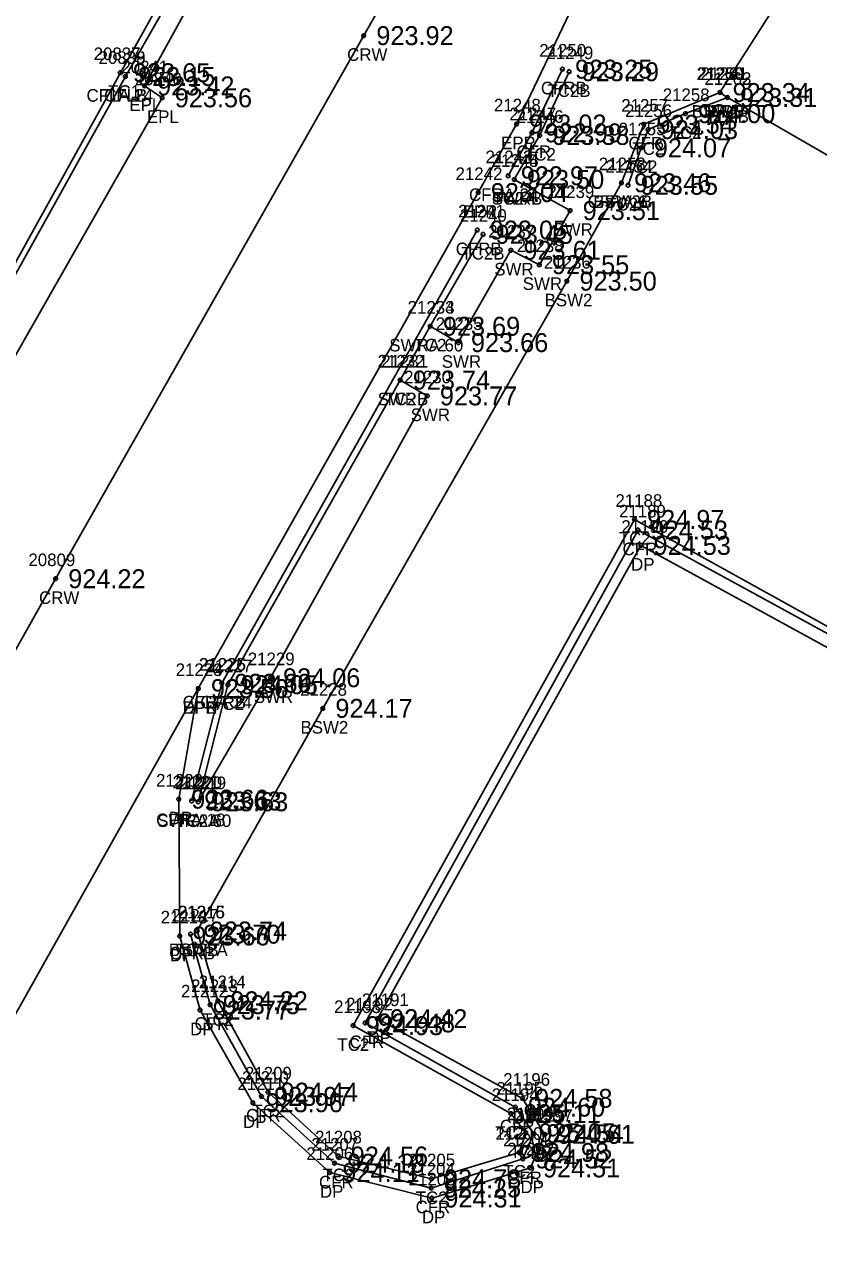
# Model space of a CAD drawing. Extents: x 1576181 to 1577685, y 1099396 to 1101490.
# Drawn here: x 1576844.5 to 1576907.5, y 1100279.9 to 1100377.3 of the extents above; entities that cross this region are included whole.
import ezdxf

# ---------------------------------------------------------------- set-up
doc = ezdxf.new("R2010")
doc.units = 0
for name, color, linetype in [('RD_DTM_BkLn1', 7, 'Continuous'), ('RD_DTM_BkLn2', 7, 'Continuous'), ('RD_EX_Conc', 7, 'Continuous'), ('RD_EX_Conc_txCode', 7, 'Continuous'), ('RD_EX_Driveway', 7, 'Continuous'), ('RD_EX_Driveway_txCode', 7, 'Continuous'), ('RD_EX_Road', 7, 'Continuous'), ('RD_EX_Road_txCode', 7, 'Continuous'), ('RD_EX_TX_Conc_ELEV', 7, 'Continuous'), ('RD_EX_TX_Driveway_ELEV', 7, 'Continuous'), ('RD_EX_TX_Road_ELEV', 7, 'Continuous'), ('RD_HC_Survey_ELEV', 7, 'Continuous'), ('RD_HC_Survey_txCode', 7, 'Continuous'), ('RD_SMD_Locator', 7, 'Continuous')]:
    doc.layers.add(name, color=color, linetype=linetype)

msp = doc.modelspace()

# ---------------------------------------------------------------- linework, layer by layer
at = {"layer": 'RD_DTM_BkLn1'}
msp.add_lwpolyline([(1576435.959, 1099635.472), (1576469.98, 1099685.91), (1576496.508, 1099728.461), (1576522.669, 1099770.846), (1576549.059, 1099813.404), (1576563.36, 1099837.201), (1576575.086, 1099855.947), (1576600.753, 1099898.956), (1576625.567, 1099942.138), (1576652.375, 1099988.914), (1576675.029, 1100029.122), (1576699.512, 1100072.437), (1576723.525, 1100115.704), (1576748.078, 1100158.53), (1576774.135, 1100203.854), (1576797.974, 1100246.518), (1576822.461, 1100289.822), (1576846.927, 1100333.353), (1576871.373, 1100376.464), (1576888.271, 1100406.22)], dxfattribs=at)
at = {"layer": 'RD_DTM_BkLn2'}
for points in [[(1576569.711, 1099889.13), (1576574.557, 1099891.336), (1576579.266, 1099894.472), (1576584.192, 1099899.549), (1576592.247, 1099913.589), (1576612.839, 1099949.867), (1576637.542, 1099993.053), (1576637.542, 1099993.053), (1576662.194, 1100036.338), (1576686.674, 1100079.686), (1576711.458, 1100123.123), (1576735.923, 1100166.594), (1576760.755, 1100210.189), (1576785.214, 1100253.551), (1576809.128, 1100296.431), (1576833.847, 1100340.609), (1576852.062, 1100373.523), (1576858.657, 1100385.374)], [(1576883.322, 1100365.048), (1576885.33, 1100368.539), (1576887.663, 1100373.598)], [(1576892.348, 1100364.583), (1576893.39, 1100367.555), (1576893.933, 1100369.003), (1576896.892, 1100370.27), (1576900.229, 1100371.557)], [(1576858.248, 1100315.646), (1576860.602, 1100324.935), (1576874.266, 1100349.12), (1576876.652, 1100353.396), (1576880.838, 1100360.691)], [(1576981.641, 1100308.772), (1576944.221, 1100331.974), (1576924.823, 1100343.94), (1576916.376, 1100330.898), (1576913.272, 1100328.019), (1576909.644, 1100328.751), (1576892.858, 1100338.06), (1576870.533, 1100297.878), (1576883.045, 1100290.892), (1576884.239, 1100289.373), (1576883.702, 1100287.814), (1576876.741, 1100285.714), (1576869.346, 1100287.53), (1576863.783, 1100292.601), (1576859.799, 1100299.85), (1576858.159, 1100305.393)]]:
    msp.add_lwpolyline(points, dxfattribs=at)
at = {"layer": 'RD_EX_Conc'}
for points in [[(1576569.868, 1099888.686), (1576574.844, 1099890.862), (1576574.844, 1099890.862), (1576579.65, 1099894.152), (1576584.72, 1099899.292), (1576592.679, 1099913.301), (1576613.452, 1099949.723), (1576638.024, 1099992.781), (1576638.024, 1099992.781), (1576662.599, 1100036.053), (1576687.141, 1100079.444), (1576711.907, 1100122.93), (1576736.416, 1100166.347), (1576761.24, 1100209.96), (1576785.667, 1100253.173), (1576809.571, 1100296.248), (1576834.314, 1100340.558), (1576852.459, 1100373.219), (1576852.459, 1100373.219), (1576859.244, 1100385.101)], [(1576899.64, 1100371.947), (1576906.579, 1100382.841), (1576904.274, 1100384.162), (1576904.199, 1100384.423)], [(1576882.832, 1100365.339), (1576884.725, 1100368.746), (1576887.135, 1100373.802)], [(1576891.82, 1100364.783), (1576893.604, 1100369.429), (1576899.64, 1100371.947)], [(1576876.652, 1100353.396), (1576878.88, 1100352.096), (1576883.047, 1100359.426), (1576885.307, 1100358.28), (1576887.745, 1100362.574), (1576883.322, 1100365.048)], [(1576858.159, 1100305.393), (1576868.123, 1100323.063), (1576887.49, 1100356.975), (1576891.82, 1100364.783)], [(1576857.719, 1100315.713), (1576860.106, 1100325.056), (1576860.106, 1100325.056), (1576880.379, 1100361.032)], [(1576858.248, 1100315.646), (1576863.967, 1100325.491), (1576876.416, 1100347.866), (1576874.266, 1100349.12)], [(1576981.4, 1100308.175), (1576943.854, 1100331.434), (1576924.982, 1100343.186), (1576916.835, 1100330.69), (1576913.186, 1100327.347), (1576909.365, 1100328.339), (1576893.139, 1100337.219), (1576871.484, 1100298.091), (1576883.401, 1100291.404), (1576884.862, 1100289.303), (1576883.985, 1100287.299), (1576876.72, 1100284.984), (1576869.052, 1100286.957), (1576863.263, 1100292.262), (1576859.183, 1100299.543), (1576857.641, 1100305.136)]]:
    msp.add_lwpolyline(points, dxfattribs=at)
at = {"layer": 'RD_EX_Driveway'}
for points in [[(1576899.64, 1100371.947), (1576900.229, 1100371.557), (1576947.086, 1100344.489), (1576990.818, 1100317.698)], [(1576980.993, 1100307.534), (1576943.247, 1100330.682), (1576925.325, 1100342), (1576917.589, 1100330.217), (1576913.446, 1100326.455), (1576909.081, 1100327.403), (1576893.369, 1100335.997), (1576872.46, 1100298.43), (1576883.975, 1100292.106), (1576885.751, 1100289.247), (1576884.594, 1100286.58), (1576876.771, 1100284.193), (1576868.68, 1100286.222), (1576862.578, 1100291.757), (1576858.385, 1100299.115), (1576856.774, 1100304.988), (1576856.691, 1100315.855), (1576858.248, 1100324.631)]]:
    msp.add_lwpolyline(points, dxfattribs=at)
at = {"layer": 'RD_EX_Road'}
for points in [[(1576574.844, 1099890.862), (1576581.171, 1099887.16), (1576595.394, 1099911.974), (1576615.874, 1099948.174), (1576640.557, 1099991.404), (1576640.557, 1099991.404), (1576664.878, 1100034.189), (1576689.843, 1100078.058), (1576714.218, 1100121.186), (1576739.079, 1100164.658), (1576764.147, 1100209.109), (1576788.309, 1100251.8), (1576812.145, 1100294.456), (1576837.057, 1100339.374), (1576855.378, 1100371.527), (1576853.98, 1100372.475), (1576862.984, 1100388.862), (1576865.16, 1100391.948), (1576873.145, 1100402.798), (1576877.449, 1100410.316)], [(1576663.307, 1099979.534), (1576687.432, 1100021.526), (1576712.032, 1100065.104), (1576738.416, 1100112.144), (1576760.611, 1100151.412), (1576785.777, 1100195.961), (1576800.589, 1100221.872), (1576817.543, 1100252.084), (1576858.248, 1100324.631), (1576880.454, 1100364.005), (1576883.5, 1100369.448), (1576896.98, 1100397.709)]]:
    msp.add_lwpolyline(points, dxfattribs=at)
at = {"layer": 'RD_SMD_Locator'}
for centre in [(1576871.373, 1100376.464), (1576887.135, 1100373.802), (1576887.663, 1100373.598), (1576852.062, 1100373.523), (1576852.459, 1100373.219), (1576852.459, 1100373.219), (1576853.98, 1100372.475), (1576899.64, 1100371.947), (1576899.64, 1100371.947), (1576899.64, 1100371.947), (1576855.378, 1100371.527), (1576900.229, 1100371.557), (1576900.229, 1100371.557), (1576896.892, 1100370.27), (1576883.5, 1100369.448), (1576884.725, 1100368.746), (1576893.604, 1100369.429), (1576893.933, 1100369.003), (1576885.33, 1100368.539), (1576893.39, 1100367.555), (1576882.832, 1100365.339), (1576883.322, 1100365.048), (1576883.322, 1100365.048), (1576891.82, 1100364.783), (1576891.82, 1100364.783), (1576880.454, 1100364.005), (1576892.348, 1100364.583), (1576887.745, 1100362.574), (1576880.379, 1100361.032), (1576880.838, 1100360.691), (1576883.047, 1100359.426), (1576885.307, 1100358.28), (1576887.49, 1100356.975), (1576876.652, 1100353.396), (1576876.652, 1100353.396), (1576878.88, 1100352.096), (1576874.266, 1100349.12), (1576874.266, 1100349.12), (1576876.416, 1100347.866), (1576892.858, 1100338.06), (1576893.139, 1100337.219), (1576893.369, 1100335.997), (1576846.927, 1100333.353), (1576860.106, 1100325.056), (1576860.106, 1100325.056), (1576860.602, 1100324.935), (1576863.967, 1100325.491), (1576858.248, 1100324.631), (1576858.248, 1100324.631), (1576868.123, 1100323.063), (1576856.691, 1100315.855), (1576857.719, 1100315.713), (1576858.248, 1100315.646), (1576858.248, 1100315.646), (1576858.159, 1100305.393), (1576858.159, 1100305.393), (1576856.774, 1100304.988), (1576857.641, 1100305.136), (1576859.183, 1100299.543), (1576859.799, 1100299.85), (1576858.385, 1100299.115), (1576870.533, 1100297.878), (1576871.484, 1100298.091), (1576872.46, 1100298.43), (1576862.578, 1100291.757), (1576863.263, 1100292.262), (1576863.783, 1100292.601), (1576883.975, 1100292.106), (1576883.045, 1100290.892), (1576883.401, 1100291.404), (1576884.239, 1100289.373), (1576884.862, 1100289.303), (1576885.751, 1100289.247), (1576883.702, 1100287.814), (1576869.052, 1100286.957), (1576869.346, 1100287.53), (1576883.985, 1100287.299), (1576868.68, 1100286.222), (1576884.594, 1100286.58), (1576876.72, 1100284.984), (1576876.741, 1100285.714), (1576876.771, 1100284.193)]:
    msp.add_circle(centre, 0.15, dxfattribs=at)

# ---------------------------------------------------------------- texts
at = {"layer": 'RD_EX_Conc_txCode'}
for s, p in [('21250', (1576885.301, 1100374.802)), ('20837', (1576849.944, 1100374.523)), ('20838', (1576850.34, 1100374.219)), ('20839', (1576850.34, 1100374.219)), ('21249', (1576885.868, 1100374.598)), ('21260', (1576897.781, 1100372.947)), ('21259', (1576897.844, 1100372.947)), ('CFRB', (1576885.434, 1100371.802)), ('21263', (1576898.411, 1100372.557)), ('CFLA 24', (1576849.38, 1100371.219)), ('CFLB', (1576850.781, 1100371.219)), ('TC1', (1576851.101, 1100371.523)), ('TC2B', (1576885.947, 1100371.598)), ('21258', (1576895.097, 1100371.27)), ('21257', (1576891.809, 1100370.429)), ('21256', (1576892.115, 1100370.003)), ('BSW2A', (1576897.388, 1100369.947)), ('CFRB', (1576897.939, 1100369.947)), ('21247', (1576882.93, 1100369.746)), ('21246', (1576883.511, 1100369.539)), ('TC2B', (1576898.513, 1100369.557)), ('21255', (1576891.595, 1100368.555)), ('TC2', (1576895.648, 1100368.27)), ('CFR', (1576892.375, 1100367.429)), ('TC2', (1576892.689, 1100367.003)), ('21243', (1576881.036, 1100366.339)), ('21244', (1576881.526, 1100366.048)), ('21245', (1576881.526, 1100366.048)), ('CFR', (1576883.497, 1100366.746)), ('TC2', (1576884.086, 1100366.539)), ('21252', (1576890.024, 1100365.783)), ('21253', (1576890.024, 1100365.783)), ('21254', (1576890.553, 1100365.583)), ('TC2', (1576892.146, 1100365.555)), ('CFRA 24', (1576879.729, 1100363.339)), ('SWRB', (1576881.534, 1100363.048)), ('TC2A', (1576881.589, 1100363.048)), ('21239', (1576885.95, 1100363.574)), ('21241', (1576878.867, 1100362.032)), ('CFRA 6', (1576889.143, 1100362.783)), ('BSW2B', (1576889.583, 1100362.783)), ('TC2A', (1576890.616, 1100362.583)), ('21240', (1576879.004, 1100361.691)), ('21237', (1576881.252, 1100360.426)), ('SWR', (1576886.43, 1100360.574)), ('21238', (1576883.512, 1100359.28)), ('CFRB', (1576878.678, 1100359.032)), ('TC2B', (1576879.122, 1100358.691)), ('SWR', (1576881.732, 1100357.426)), ('21236', (1576885.671, 1100357.975)), ('SWR', (1576883.992, 1100356.28)), ('21233', (1576874.857, 1100354.396)), ('21234', (1576874.857, 1100354.396)), ('BSW2', (1576885.726, 1100354.975)), ('21235', (1576877.085, 1100353.096)), ('SWRA 60', (1576873.4, 1100351.396)), ('TC2', (1576875.408, 1100351.396)), ('21232', (1576872.471, 1100350.12)), ('21231', (1576872.754, 1100350.12)), ('SWR', (1576877.565, 1100350.096)), ('21230', (1576874.581, 1100348.866)), ('SWRB', (1576872.479, 1100347.12)), ('TC2', (1576873.022, 1100347.12)), ('SWR', (1576875.101, 1100345.866)), ('21188', (1576891.346, 1100339.06)), ('21189', (1576891.627, 1100338.219)), ('TC2', (1576891.614, 1100336.06)), ('CFR', (1576891.91, 1100335.219)), ('21226', (1576858.287, 1100326.056)), ('21225', (1576858.31, 1100326.056)), ('21227', (1576858.806, 1100325.935)), ('21229', (1576862.172, 1100326.491)), ('21228', (1576866.328, 1100324.063)), ('CFRA 24', (1576857.003, 1100323.056)), ('CFRB', (1576858.405, 1100323.056)), ('SWR', (1576862.652, 1100323.491)), ('TC2', (1576859.358, 1100322.935)), ('BSW2', (1576866.359, 1100321.063)), ('21221', (1576856.207, 1100316.713)), ('21220', (1576856.413, 1100316.646)), ('21219', (1576856.736, 1100316.646)), ('CFRA 18', (1576854.9, 1100313.713)), ('SWRA 60', (1576854.996, 1100313.646)), ('TC2A', (1576856.516, 1100313.646)), ('21217', (1576856.129, 1100306.136)), ('21216', (1576856.624, 1100306.393)), ('21215', (1576856.648, 1100306.393)), ('CFRB', (1576855.94, 1100303.136)), ('BSW2A', (1576855.907, 1100303.393)), ('TC2B', (1576856.443, 1100303.393)), ('21214', (1576858.287, 1100300.85)), ('21213', (1576857.671, 1100300.543)), ('21193', (1576869.021, 1100298.878)), ('21192', (1576869.972, 1100299.091)), ('TC2', (1576858.555, 1100297.85)), ('CFR', (1576857.954, 1100297.543)), ('TC2', (1576869.289, 1100295.878)), ('CFR', (1576870.255, 1100296.091)), ('21210', (1576861.712, 1100293.262)), ('21209', (1576861.949, 1100293.601)), ('21194', (1576881.533, 1100291.892)), ('21195', (1576881.889, 1100292.404)), ('CFR', (1576862.035, 1100290.262)), ('TC2', (1576862.539, 1100290.601)), ('21199', (1576882.727, 1100290.373)), ('21198', (1576883.351, 1100290.303)), ('TC2', (1576881.801, 1100288.892)), ('CFR', (1576882.173, 1100289.404)), ('21207', (1576867.217, 1100287.957)), ('21208', (1576867.511, 1100288.53)), ('21200', (1576881.827, 1100288.814)), ('21201', (1576882.434, 1100288.299)), ('TC2', (1576882.995, 1100287.373)), ('CFR', (1576883.634, 1100287.303)), ('21204', (1576874.885, 1100285.984)), ('21205', (1576874.907, 1100286.714)), ('TC2', (1576868.102, 1100285.53)), ('TC2', (1576882.457, 1100285.814)), ('CFR', (1576882.757, 1100285.299)), ('CFR', (1576867.824, 1100284.957)), ('TC2', (1576875.497, 1100283.714)), ('CFR', (1576875.492, 1100282.984))]:
    msp.add_text(s, height=1, dxfattribs=at).set_placement(p)
at = {"layer": 'RD_EX_Driveway_txCode'}
for s, p in [('21261', (1576898.104, 1100372.947)), ('21262', (1576898.411, 1100372.557)), ('DPA', (1576898.372, 1100369.947)), ('DP', (1576899.45, 1100369.557)), ('21190', (1576891.818, 1100336.997)), ('DP', (1576892.589, 1100333.997)), ('21223', (1576856.452, 1100325.631)), ('DPB', (1576856.996, 1100322.631)), ('21222', (1576854.896, 1100316.855)), ('DP', (1576855.911, 1100313.855)), ('21218', (1576855.263, 1100305.988)), ('DP', (1576855.995, 1100302.988)), ('21212', (1576856.873, 1100300.115)), ('21191', (1576871.232, 1100299.43)), ('DP', (1576857.605, 1100297.115)), ('DP', (1576871.681, 1100296.43)), ('21211', (1576861.349, 1100292.757)), ('21196', (1576882.439, 1100293.106)), ('DP', (1576883.195, 1100290.106)), ('21197', (1576884.239, 1100290.247)), ('DP', (1576861.798, 1100289.757)), ('21206', (1576866.822, 1100287.222)), ('21202', (1576882.759, 1100287.58)), ('DP', (1576884.971, 1100287.247)), ('21203', (1576874.936, 1100285.193)), ('DP', (1576867.9, 1100284.222)), ('DP', (1576883.814, 1100284.58)), ('DP', (1576875.991, 1100282.193))]:
    msp.add_text(s, height=1, dxfattribs=at).set_placement(p)
at = {"layer": 'RD_EX_Road_txCode'}
for s, p in [('20841', (1576852.145, 1100373.475)), ('20840', (1576853.22, 1100372.527)), ('EPL', (1576852.775, 1100370.475)), ('21248', (1576881.705, 1100370.448)), ('EPL', (1576854.173, 1100369.527)), ('EPR', (1576882.272, 1100367.448)), ('21242', (1576878.658, 1100365.005)), ('EPR', (1576879.225, 1100362.005)), ('21224', (1576856.452, 1100325.631)), ('EPR', (1576857.019, 1100322.631))]:
    msp.add_text(s, height=1, dxfattribs=at).set_placement(p)
at = {"layer": 'RD_EX_TX_Conc_ELEV'}
for s, p in [('923.65', (1576853.062, 1100372.773)), ('923.15', (1576853.459, 1100372.469)), ('923.15', (1576853.459, 1100372.469)), ('923.25', (1576888.135, 1100373.052)), ('923.29', (1576888.663, 1100372.848)), ('923.34', (1576900.64, 1100371.197)), ('923.34', (1576900.64, 1100371.197)), ('923.31', (1576901.229, 1100370.807)), ('924.00', (1576897.892, 1100369.52)), ('923.54', (1576894.604, 1100368.679)), ('922.99', (1576885.725, 1100367.996)), ('923.38', (1576886.33, 1100367.789)), ('924.03', (1576894.933, 1100368.253)), ('924.07', (1576894.39, 1100366.805)), ('922.97', (1576883.832, 1100364.589)), ('923.50', (1576884.322, 1100364.298)), ('923.50', (1576884.322, 1100364.298)), ('923.46', (1576892.82, 1100364.033)), ('923.46', (1576892.82, 1100364.033)), ('923.55', (1576893.348, 1100363.833)), ('923.51', (1576888.745, 1100361.824)), ('923.05', (1576881.379, 1100360.282)), ('923.45', (1576881.838, 1100359.941)), ('923.61', (1576884.047, 1100358.676)), ('923.55', (1576886.307, 1100357.53)), ('923.50', (1576888.49, 1100356.225)), ('923.69', (1576877.652, 1100352.646)), ('923.69', (1576877.652, 1100352.646)), ('923.66', (1576879.88, 1100351.346)), ('923.74', (1576875.266, 1100348.37)), ('923.74', (1576875.266, 1100348.37)), ('923.77', (1576877.416, 1100347.116)), ('924.97', (1576893.858, 1100337.31)), ('924.53', (1576894.139, 1100336.469)), ('924.06', (1576864.967, 1100324.741)), ('923.60', (1576861.106, 1100324.306)), ('923.60', (1576861.106, 1100324.306)), ('924.05', (1576861.602, 1100324.185)), ('924.17', (1576869.123, 1100322.313)), ('923.63', (1576858.719, 1100314.963)), ('923.63', (1576859.248, 1100314.896)), ('923.63', (1576859.248, 1100314.896)), ('923.70', (1576858.641, 1100304.386)), ('923.74', (1576859.159, 1100304.643)), ('923.74', (1576859.159, 1100304.643)), ('924.22', (1576860.799, 1100299.1)), ('923.75', (1576860.183, 1100298.793)), ('924.93', (1576871.533, 1100297.128)), ('924.48', (1576872.484, 1100297.341)), ('923.97', (1576864.263, 1100291.512)), ('924.44', (1576864.783, 1100291.851)), ('924.60', (1576884.401, 1100290.654)), ('925.11', (1576884.045, 1100290.142)), ('925.05', (1576885.239, 1100288.623)), ('924.54', (1576885.862, 1100288.553)), ('924.56', (1576870.346, 1100286.78)), ('924.98', (1576884.702, 1100287.064)), ('924.52', (1576884.985, 1100286.549)), ('924.13', (1576870.052, 1100286.207)), ('924.78', (1576877.741, 1100284.964)), ('924.25', (1576877.72, 1100284.234))]:
    msp.add_text(s, height=1.5, dxfattribs=at).set_placement(p)
at = {"layer": 'RD_EX_TX_Driveway_ELEV'}
for s, p in [('923.34', (1576900.64, 1100371.197)), ('923.31', (1576901.229, 1100370.807)), ('924.53', (1576894.369, 1100335.247)), ('923.56', (1576859.248, 1100323.881)), ('923.66', (1576857.691, 1100315.105)), ('923.66', (1576857.774, 1100304.238)), ('923.77', (1576859.385, 1100298.365)), ('924.42', (1576873.46, 1100297.68)), ('924.58', (1576884.975, 1100291.356)), ('923.96', (1576863.578, 1100291.007)), ('924.61', (1576886.751, 1100288.497)), ('924.11', (1576869.68, 1100285.472)), ('924.51', (1576885.594, 1100285.83)), ('924.31', (1576877.771, 1100283.443))]:
    msp.add_text(s, height=1.5, dxfattribs=at).set_placement(p)
at = {"layer": 'RD_EX_TX_Road_ELEV'}
for s, p in [('923.42', (1576854.98, 1100371.725)), ('923.56', (1576856.378, 1100370.777)), ('923.02', (1576884.5, 1100368.698)), ('923.04', (1576881.454, 1100363.255)), ('923.56', (1576859.248, 1100323.881))]:
    msp.add_text(s, height=1.5, dxfattribs=at).set_placement(p)
at = {"layer": 'RD_HC_Survey_ELEV'}
for s, p in [('923.92', (1576872.373, 1100375.714)), ('924.22', (1576847.927, 1100332.603))]:
    msp.add_text(s, height=1.5, dxfattribs=at).set_placement(p)
at = {"layer": 'RD_HC_Survey_txCode'}
for s, p in [('CRW', (1576870.058, 1100374.464)), ('20809', (1576844.769, 1100334.353)), ('CRW', (1576845.612, 1100331.353))]:
    msp.add_text(s, height=1, dxfattribs=at).set_placement(p)

doc.saveas('drawing.dxf')
